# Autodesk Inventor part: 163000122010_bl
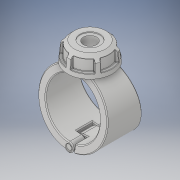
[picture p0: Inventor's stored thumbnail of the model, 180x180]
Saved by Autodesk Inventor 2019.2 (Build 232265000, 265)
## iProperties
Created: 2022-02
Part Number: 163000122010_bl
Material: Generic
Description: Plassadle Threaded 122x1''
Document SubType Name: Modeling
Designer: comp2
Density: 1 g/cm^3
Appearance: Default
Author: comp2
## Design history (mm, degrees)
derived "16300.ipt"
feature "Solid1::16300.ipt" dims "ScaleForDerivedMember" = 10
feature "Solid2::16300.ipt" dims "ScaleForDerivedMember" = 10
feature "Solid3::16300.ipt" dims "ScaleForDerivedMember" = 10
feature "Solid4::16300.ipt" dims "ScaleForDerivedMember" = 10
tag "TaggingFeature1"
body "Solid1"
body "Solid2"
body "Solid3"
body "Solid4"
other parameters: "d0" = 122 [user parameter], "d2" = 157 [user parameter], "d3" = 61 [user parameter], "d7" = 149.15 [user parameter], "d8" = 85 deg [user parameter], "d9" = 45 deg [user parameter], "d10" = 102 [user parameter], "d11" = 49 [user parameter], "d12" = 29.2495 [user parameter], "d13" = 42.84 [user parameter], "d14" = 45.4365 [user parameter], "d42" = 3.5 [user parameter], "d49" = 3.14 [user parameter], "d51" = 0 [user parameter], "d52" = 24.5 [user parameter], "d53" = 86.35 [user parameter], "d54" = 35 [user parameter], "d55" = 0 [user parameter], "d59" = 0 [user parameter], "d61" = 0 [user parameter], "d62" = 35 [user parameter], "d63" = 0 [user parameter], "d65" = 0 [user parameter], "d67" = 0 [user parameter], "d69" = 0 [user parameter], "d70" = 1 [user parameter], "d71" = 96 [user parameter], "d72" = 0 [user parameter], "d73" = 2 [user parameter], "d78" = 86.7 [user parameter], "d79" = 5.1 [user parameter], "d80" = 60 deg [user parameter], "d81" = 5.1 [user parameter], "d84" = 0 [user parameter], "d85" = 1 [user parameter], "d87" = 360 deg [user parameter], "d122" = 52 [user parameter], "d124" = 42.80128 [user parameter], "d125" = 2.08925 [user parameter], "d127" = 198 [user parameter], "d129" = 30.291 [user parameter], "d130" = 25.74735 [user parameter], "d131" = 33.8 [user parameter], "d132" = 45 deg [user parameter], "d133" = 23.66 [user parameter], "d134" = 15.1455 [user parameter], "d136" = 0 [user parameter], "d138" = 0 [user parameter], "d" = 122 [user parameter], "d1" = 25 [user parameter], "B" = 157 [user parameter], "E_" = 54 [user parameter], "E1" = 102 [user parameter], "H1" = 198 [user parameter], "H2" = 52 [user parameter], "H3" = 78 [user parameter], "H_costum" = 49 [user parameter], "Rp" = 30.291 [user parameter], "d128" = 41.785 [user parameter]
